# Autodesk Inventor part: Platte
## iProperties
Created: 2007-01
Material: Standard
Description: Blech lt. Tab.
Document SubType Name: Blech
Designer: R.Pilz
Title: Platte
Author: R.Pilz
ArtNrPrefix: HZ
ArtNrAuto: 0
EDVNum=ArtNr: 0
Bez=Mat: 0
ArtNrBackSpace: 0
EDVNrBackSpace: 0
EDVNrAuto: 0
ProdGruppe: ÜKWW
ProdBezeichnung: Blende
ArtNr: lt. Tab.
EDVNr: lt. Tab
KommaZuschnitt: 0
Zeichnungsnummer: 0G24 TE ST
Konstrukteur: R.Pilz
Erstellungsdatum: 10.01.2007
GesGewicht: 0,1kg
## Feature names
1. Abgeleiteter Körper1 [Tagging]
